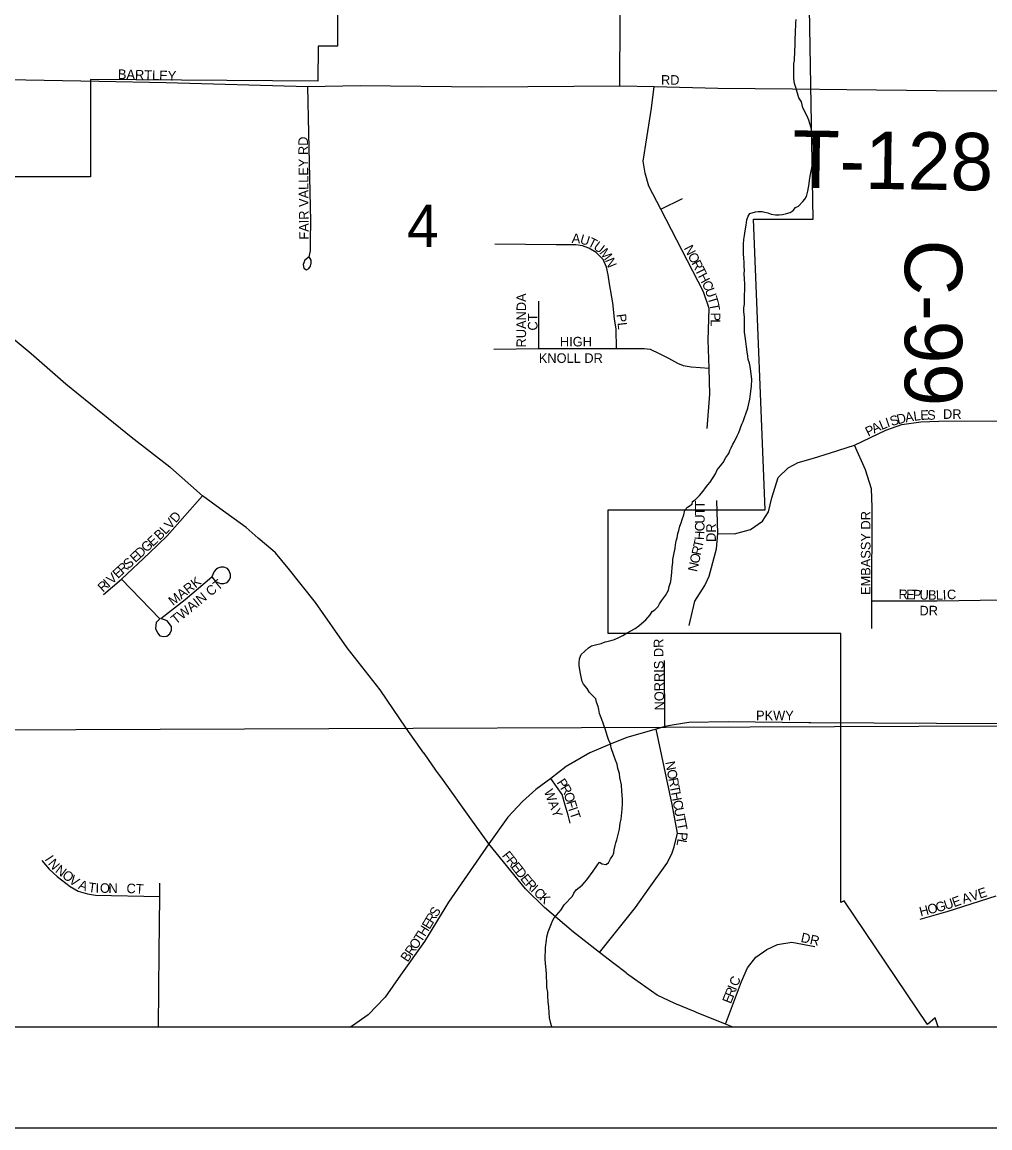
# Model space of a CAD drawing. Extents: x 8.5 to 81.5, y -1.2 to 22.4.
# Drawn here: x 51.227 to 52.184, y 14.351 to 15.445 of the extents above; entities that cross this region are included whole.
import ezdxf

# ---------------------------------------------------------------- set-up
doc = ezdxf.new("R2010")
doc.units = 0
for name, color, linetype in [('GM_X_City_Street', 7, 'Continuous'), ('GM_X_City_Street_Text', 7, 'Continuous'), ('GM_X_Corporation', 7, 'Continuous'), ('GM_X_County', 7, 'Continuous'), ('GM_X_County_Road', 7, 'Continuous'), ('GM_X_County_Road_Text', 7, 'Continuous'), ('GM_X_Minor_River', 7, 'Continuous'), ('GM_X_Section', 7, 'Continuous'), ('GM_X_Section_Text', 7, 'Continuous'), ('GM_X_Township', 7, 'Continuous'), ('GM_X_Township_Road', 7, 'Continuous'), ('GM_X_Township_Road_Text', 7, 'Continuous'), ('GM_X_Township_Subdivision', 7, 'Continuous'), ('GM_X_Township_Subdivision_Text', 7, 'Continuous'), ('SH_Data', 7, 'Continuous')]:
    doc.layers.add(name, color=color, linetype=linetype)

msp = doc.modelspace()

# ---------------------------------------------------------------- linework, layer by layer
at = {"layer": 'GM_X_City_Street'}
for points in [[(51.8184, 15.3819), (51.8187, 15.4496), (51.8192, 15.5596), (51.8199, 15.5865), (51.8185, 15.5979), (51.8172, 15.6073), (51.8137, 15.6169), (51.804, 15.6315), (51.7923, 15.6432), (51.7791, 15.6529), (51.7646, 15.6584), (51.7518, 15.6615), (51.7335, 15.6612), (51.6527, 15.6609)], [(51.3031, 15.3865), (51.3695, 15.3852), (51.5095, 15.3812), (51.5614, 15.3822), (51.6817, 15.381), (51.8184, 15.3819), (51.8522, 15.3812), (51.9151, 15.3797), (51.9892, 15.3789)], [(51.5109, 15.2126), (51.5065, 15.2093), (51.505, 15.2052), (51.5057, 15.2014), (51.5083, 15.1999), (51.5106, 15.201), (51.5121, 15.2033), (51.5129, 15.2063), (51.5129, 15.2095), (51.5109, 15.2126), (51.5121, 15.2186), (51.5122, 15.2294), (51.5124, 15.2478), (51.5106, 15.3349), (51.5095, 15.3812)], [(51.9048, 15.0429), (51.9075, 15.0769), (51.9066, 15.1026), (51.9057, 15.1302), (51.9066, 15.1614), (51.9011, 15.1779), (51.8588, 15.2597), (51.8469, 15.2826), (51.8432, 15.2955), (51.8414, 15.3074), (51.8451, 15.3304), (51.8497, 15.3598), (51.8522, 15.3812)], [(51.8588, 15.2597), (51.8802, 15.2705)], [(51.3735, 15.004), (51.373, 15.0044), (51.3347, 15.0342), (51.3066, 15.0568), (51.27, 15.0866), (51.2359, 15.1168), (51.2201, 15.13), (51.2001, 15.1505), (51.169, 15.1863), (51.1432, 15.2208), (51.1225, 15.2467), (51.1174, 15.2524)], [(51.815, 15.1221), (51.8146, 15.141), (51.8131, 15.1512), (51.8112, 15.167), (51.8082, 15.1859), (51.8067, 15.1949), (51.8052, 15.2025), (51.8018, 15.21), (51.795, 15.2168), (51.7875, 15.2213), (51.7814, 15.2236), (51.7746, 15.2247), (51.7554, 15.2247), (51.6947, 15.2251)], [(51.7381, 15.1221), (51.7381, 15.1687)], [(51.6935, 15.1214), (51.7381, 15.1221), (51.815, 15.1221), (51.8422, 15.1218), (51.8482, 15.1214), (51.8572, 15.1169), (51.8663, 15.1123), (51.8753, 15.1074), (51.881, 15.1052), (51.8889, 15.1037), (51.9066, 15.1026)], [(51.4748, 14.9221), (51.4604, 14.9343), (51.4484, 14.9447), (51.4225, 14.9637), (51.4052, 14.976), (51.3735, 15.004)], [(51.3072, 14.8784), (51.3252, 14.8938), (51.3524, 14.9195), (51.3704, 14.9364), (51.4052, 14.976)], [(51.6245, 14.7214), (51.607, 14.7462), (51.5811, 14.7841), (51.5484, 14.8256), (51.5171, 14.8705), (51.4902, 14.9046), (51.4775, 14.9198), (51.4748, 14.9221)], [(51.3252, 14.8938), (51.3631, 14.8543), (51.3594, 14.8509), (51.3589, 14.8448), (51.3609, 14.8404), (51.363, 14.8376), (51.3671, 14.8368), (51.3699, 14.8373), (51.373, 14.8396), (51.3748, 14.843), (51.3745, 14.8468), (51.3704, 14.8525), (51.3642, 14.8546), (51.3881, 14.8735), (51.4146, 14.8959), (51.4182, 14.8912), (51.4231, 14.8892), (51.4264, 14.8892), (51.4297, 14.8905), (51.4318, 14.8925), (51.4331, 14.8956), (51.4331, 14.8984), (51.4318, 14.902), (51.43, 14.9043), (51.4264, 14.9054), (51.4236, 14.9054), (51.4205, 14.9046), (51.4192, 14.9036), (51.4189, 14.9036), (51.4169, 14.9013), (51.4156, 14.8982), (51.4146, 14.8959)], [(51.8629, 14.7479), (51.8625, 14.8132)], [(52.0052, 14.7513), (51.9257, 14.7523), (51.8867, 14.7518), (51.8721, 14.7495), (51.8629, 14.7479), (51.8542, 14.7453), (51.8252, 14.7368), (51.8079, 14.73), (51.7886, 14.7216), (51.7652, 14.7083), (51.7501, 14.6963), (51.7351, 14.6853), (51.722, 14.6737), (51.7076, 14.6582), (51.6887, 14.6317)], [(51.7982, 14.5242), (51.8337, 14.5687), (51.8472, 14.5877), (51.8647, 14.6122), (51.8697, 14.6217), (51.8722, 14.6287), (51.8752, 14.6422), (51.8702, 14.6707), (51.8542, 14.7453)], [(51.6419, 14.6969), (51.6363, 14.7047), (51.6246, 14.7213), (51.6245, 14.7214)], [(51.6887, 14.6317), (51.6708, 14.6564), (51.642, 14.6967), (51.6419, 14.6969)], [(51.769, 14.6522), (51.7671, 14.6601), (51.7641, 14.6699), (51.7611, 14.6805), (51.7501, 14.6963)], [(51.6887, 14.6317), (51.6487, 14.574), (51.625, 14.535), (51.6012, 14.5016), (51.586, 14.4799), (51.5692, 14.4626), (51.5537, 14.4514), (51.5522, 14.4506)], [(51.77, 14.5462), (51.7436, 14.5687), (51.7251, 14.5872), (51.6887, 14.6317)], [(51.2463, 14.6151), (51.2535, 14.6066), (51.2614, 14.5994), (51.2745, 14.5895), (51.2824, 14.5849), (51.2916, 14.5823), (51.2995, 14.581), (51.3631, 14.5797)], [(51.3619, 14.4506), (51.3626, 14.5245), (51.3631, 14.5797), (51.3632, 14.5928)], [(51.8245, 14.5039), (51.8122, 14.5131), (51.7982, 14.5242), (51.7707, 14.5456), (51.77, 14.5462)], [(51.9227, 14.4532), (51.9387, 14.4953), (51.9447, 14.5089), (51.953, 14.5194), (51.9636, 14.527), (51.9742, 14.5322), (51.9885, 14.5345), (52.0111, 14.53)], [(51.8928, 14.4653), (51.8727, 14.4737), (51.8553, 14.482), (51.8328, 14.4976), (51.8249, 14.5035), (51.8245, 14.5039)], [(51.9295, 14.4506), (51.9227, 14.4532), (51.8942, 14.4647), (51.8928, 14.4653)]]:
    msp.add_lwpolyline(points, dxfattribs=at)
at = {"layer": 'GM_X_Corporation'}
msp.add_line((51.0687, 14.4506), (52.1333, 14.4506), dxfattribs=at)
for points in [[(51.5389, 15.7615), (51.5388, 15.4213), (51.5199, 15.4213), (51.5194, 15.3866), (51.2944, 15.3882), (51.2945, 15.2917), (51.1966, 15.2917)], [(52.1333, 14.4506), (52.1304, 14.4594), (52.1227, 14.453), (52.0404, 14.5752), (52.037, 14.5736), (52.037, 14.8399), (51.8069, 14.84), (51.8069, 14.9622), (51.9622, 14.9622), (51.9504, 15.25), (52.0096, 15.25), (52.0006, 15.7624)]]:
    msp.add_lwpolyline(points, dxfattribs=at)
at = {"layer": 'GM_X_County'}
msp.add_lwpolyline([(54.0879, 21.2506), (49.4527, 21.2506), (49.4527, 14.4506), (56.2527, 14.4506), (56.2527, 19.1108)], dxfattribs=at)
at = {"layer": 'GM_X_County_Road'}
msp.add_lwpolyline([(52.1939, 14.7505), (52.0072, 14.7513), (52.0052, 14.7513)], dxfattribs=at)
at = {"layer": 'GM_X_Minor_River'}
for points in [[(51.9905, 15.404), (51.991, 15.4071), (51.991, 15.4101), (51.9915, 15.4135), (51.992, 15.4371), (51.9924, 15.4409), (51.9925, 15.4443), (51.9929, 15.4477)], [(51.9053, 14.9869), (51.9076, 14.9895), (51.9131, 14.9978), (51.9147, 15.002), (51.9178, 15.0057), (51.9205, 15.0091), (51.9233, 15.014), (51.926, 15.0181), (51.9272, 15.0211), (51.9284, 15.0237), (51.93, 15.0271), (51.9319, 15.0298), (51.9343, 15.0354), (51.9359, 15.0388), (51.9391, 15.0471), (51.9403, 15.0498), (51.9419, 15.0547), (51.9431, 15.0573), (51.9448, 15.063), (51.9456, 15.066), (51.9464, 15.0687), (51.9469, 15.0717), (51.9477, 15.077), (51.9486, 15.0846), (51.9488, 15.0911), (51.9478, 15.0994), (51.9471, 15.104), (51.9465, 15.1075), (51.9454, 15.1109), (51.9451, 15.1143), (51.9444, 15.1185), (51.9437, 15.1235), (51.9431, 15.1288), (51.9424, 15.1338), (51.9418, 15.138), (51.9418, 15.141), (51.9416, 15.146), (51.9417, 15.1528), (51.9411, 15.1585), (51.9411, 15.1623), (51.9416, 15.1658), (51.9418, 15.176), (51.9419, 15.1787), (51.942, 15.1855), (51.9417, 15.1909), (51.9414, 15.1958), (51.9415, 15.1996), (51.9412, 15.203), (51.9413, 15.2065), (51.941, 15.2122), (51.9407, 15.2148), (51.9408, 15.2175), (51.9405, 15.2221), (51.9405, 15.2251), (51.941, 15.2297), (51.9415, 15.2339), (51.9423, 15.2384), (51.9432, 15.2441), (51.9441, 15.2494), (51.9453, 15.2528), (51.9468, 15.2554), (51.9526, 15.2572), (51.9552, 15.2575), (51.959, 15.2575), (51.9617, 15.257), (51.9647, 15.2562), (51.9681, 15.255), (51.9722, 15.2542), (51.976, 15.2541), (51.9791, 15.2544), (51.9833, 15.2554), (51.9867, 15.2565), (51.9898, 15.2584), (51.9921, 15.2614), (51.9952, 15.2628), (51.9995, 15.2673), (52.0014, 15.2699), (52.003, 15.2725), (52.0042, 15.2775), (52.0055, 15.285), (52.006, 15.2885), (52.0068, 15.2941), (52.0085, 15.3025), (52.009, 15.3074), (52.0095, 15.3146), (52.01, 15.3177), (52.0101, 15.3211), (52.0094, 15.326), (52.0084, 15.3337), (52.0078, 15.3386), (52.0074, 15.3413), (52.0053, 15.3478), (52.0035, 15.352), (51.9995, 15.3601), (51.9981, 15.3662), (51.9955, 15.3701), (51.9923, 15.3804), (51.9912, 15.3842), (51.9906, 15.3892), (51.9903, 15.393), (51.9905, 15.404)], [(51.7981, 14.6135), (51.8007, 14.6119), (51.8045, 14.6111), (51.8072, 14.613), (51.8092, 14.6167), (51.8112, 14.6201), (51.8123, 14.6228), (51.8128, 14.6258), (51.8136, 14.63), (51.8144, 14.6326), (51.8153, 14.6356), (51.8169, 14.6424), (51.8178, 14.6462), (51.8187, 14.6523), (51.8195, 14.6561), (51.8199, 14.6595), (51.8205, 14.666), (51.8209, 14.6713), (51.821, 14.6755), (51.8207, 14.68), (51.8204, 14.6835), (51.8198, 14.69), (51.8184, 14.6972), (51.8178, 14.7014), (51.8164, 14.7064), (51.8157, 14.7106), (51.8139, 14.7144), (51.8124, 14.719), (51.8096, 14.7267), (51.8089, 14.7305), (51.8071, 14.7351), (51.806, 14.7378), (51.8039, 14.7455), (51.8024, 14.7493), (51.8014, 14.752), (51.7992, 14.7581), (51.7981, 14.7608), (51.7974, 14.7646), (51.7968, 14.7677), (51.7953, 14.7719), (51.7946, 14.7753), (51.792, 14.7777), (51.7883, 14.7815), (51.7861, 14.7854), (51.7824, 14.7897), (51.7809, 14.7923), (51.7803, 14.7954), (51.7792, 14.8004), (51.7779, 14.808), (51.7779, 14.8107), (51.7784, 14.8148), (51.78, 14.819), (51.7873, 14.8257), (51.7904, 14.8275), (51.7954, 14.829), (51.7999, 14.83), (51.8038, 14.8315), (51.8083, 14.8325), (51.8129, 14.8339), (51.8179, 14.8361), (51.8214, 14.838), (51.8256, 14.8405), (51.8333, 14.8449), (51.8371, 14.8475), (51.8398, 14.8498), (51.8441, 14.8535), (51.8483, 14.8583), (51.8503, 14.8617), (51.853, 14.8632), (51.8561, 14.8665), (51.8577, 14.8692), (51.8596, 14.8722), (51.8635, 14.8774), (51.8663, 14.8827), (51.8671, 14.8865), (51.8688, 14.8914), (51.8692, 14.8944), (51.8697, 14.9001), (51.8702, 14.9055), (51.8707, 14.91), (51.8707, 14.9131), (51.8716, 14.918), (51.8729, 14.9244), (51.8733, 14.9275), (51.8741, 14.9316), (51.875, 14.9347), (51.8758, 14.9388), (51.8766, 14.9419), (51.8778, 14.946), (51.8791, 14.9494), (51.8799, 14.9528), (51.8815, 14.9574), (51.8827, 14.9619), (51.8854, 14.9649), (51.8897, 14.9678), (51.8901, 14.9705), (51.8928, 14.9723), (51.8971, 14.9764), (51.9006, 14.9806), (51.9029, 14.9839), (51.9053, 14.9869)], [(51.7509, 14.4506), (51.75, 14.4539), (51.7486, 14.4596), (51.7481, 14.4699), (51.7474, 14.4756), (51.7472, 14.481), (51.7469, 14.4848), (51.7462, 14.4894), (51.7459, 14.4943), (51.7457, 14.5004), (51.7457, 14.5031), (51.7454, 14.5065), (51.7448, 14.5137), (51.7445, 14.5172), (51.7448, 14.529), (51.7457, 14.5362), (51.7461, 14.5396), (51.7474, 14.5445), (51.7506, 14.5528), (51.7518, 14.5555), (51.7533, 14.5585), (51.7603, 14.5663), (51.7631, 14.5712), (51.7716, 14.5798), (51.7728, 14.5828), (51.7752, 14.5862), (51.7809, 14.5907), (51.7856, 14.5959), (51.7919, 14.6045), (51.7962, 14.6109), (51.7981, 14.6135)]]:
    msp.add_lwpolyline(points, dxfattribs=at)
at = {"layer": 'GM_X_Section'}
msp.add_line((51.1937, 14.4506), (52.195, 14.4506), dxfattribs=at)
msp.add_lwpolyline([(51.1955, 15.7645), (52.2033, 15.7642), (52.1975, 14.7482), (51.1961, 14.7442)], close=True, dxfattribs=at)
msp.add_lwpolyline([(52.195, 14.4506), (52.1975, 14.7482), (51.1961, 14.7442), (51.1937, 14.4506)], dxfattribs=at)
at = {"layer": 'GM_X_Township'}
msp.add_lwpolyline([(49.4527, 15.7601), (49.4527, 14.4506), (54.4602, 14.4506)], dxfattribs=at)
at = {"layer": 'GM_X_Township_Road'}
for points in [[(51.1938, 15.3886), (51.3031, 15.3865)], [(51.9892, 15.3789), (51.9893, 15.3789), (52.0428, 15.3784), (52.1312, 15.3772), (52.198, 15.3769)]]:
    msp.add_lwpolyline(points, dxfattribs=at)
at = {"layer": 'GM_X_Township_Subdivision'}
for points in [[(51.9151, 14.939), (51.9318, 14.9385), (51.9476, 14.9429), (51.9594, 14.951), (51.9655, 14.9602), (51.9688, 14.974), (51.975, 14.9941), (51.9847, 15.0038), (51.9949, 15.0091), (52.0099, 15.0134), (52.0268, 15.0186), (52.0504, 15.0262), (52.0814, 15.041), (52.0973, 15.0466), (52.1161, 15.0494), (52.1341, 15.05), (52.1974, 15.0504)], [(52.0675, 14.8449), (52.0677, 14.8719), (52.0679, 14.965), (52.0673, 14.9832), (52.0615, 15.0018), (52.0504, 15.0262)], [(51.8868, 14.8477), (51.8924, 14.8719), (51.9024, 14.8873), (51.9067, 14.8967), (51.9104, 14.9102), (51.9138, 14.9235), (51.9151, 14.939), (51.9142, 14.9716)], [(52.1964, 14.8728), (52.1322, 14.8717), (52.0677, 14.8719)], [(52.1408, 14.5643), (52.1423, 14.5648), (52.1908, 14.5803)], [(52.1156, 14.5571), (52.1408, 14.5643)]]:
    msp.add_lwpolyline(points, dxfattribs=at)
at = {"layer": 'SH_Data'}
for p, q in [((49.4527, 14.4506), (56.2527, 14.4506)), ((49.3527, 14.3506), (56.3527, 14.3506))]:
    msp.add_line(p, q, dxfattribs=at)

# ---------------------------------------------------------------- texts
at = {"layer": 'GM_X_City_Street_Text'}
for s, rotation, p in [('BARTLEY', 358.211, (51.3215, 15.3888)), ('RD', 0, (51.859, 15.383)), ('FAIR VALLEY RD', 90.5087, (51.5105, 15.2297)), ('A', 356.545, (51.7705, 15.2265)), ('U', 343.7424, (51.7782, 15.2261)), ('T', 333.2394, (51.7858, 15.2239)), ('U', 322.9072, (51.7914, 15.2211)), ('N', 296.9462, (51.8814, 15.2213)), ('M', 308.1705, (51.7976, 15.2166)), ('O', 296.9829, (51.8852, 15.2139)), ('N', 292.524, (51.8034, 15.2093)), ('R', 296.9669, (51.8889, 15.2065)), ('T', 296.9439, (51.8923, 15.1998)), ('H', 296.9677, (51.8954, 15.1938)), ('C', 296.0438, (51.8991, 15.1864)), ('U', 289.4788, (51.9023, 15.18)), ('RUANDA', 90, (51.7255, 15.123)), ('T', 286.3695, (51.905, 15.1722)), ('T', 280.4955, (51.9069, 15.1661)), ('CT', 90, (51.7368, 15.1397)), ('PL', 276.7069, (51.8149, 15.1557)), ('P', 270.4645, (51.9082, 15.1575)), ('L', 270, (51.9082, 15.1508)), ('HIGH', 0, (51.759, 15.124)), ('KNOLL DR', 0, (51.7381, 15.1077)), ('V', 48.9249, (51.3735, 14.9424)), ('D', 48.9883, (51.379, 14.9487)), ('B', 43.2578, (51.3628, 14.9316)), ('L', 47.264, (51.3688, 14.9373)), ('G', 42.6267, (51.3498, 14.9197)), ('E', 42.6454, (51.356, 14.9253)), ('E', 42.6454, (51.3388, 14.9095)), ('D', 42.6192, (51.3437, 14.914)), ('R', 42.6358, (51.3265, 14.8982)), ('S', 42.643, (51.3321, 14.9033)), ('V', 42.6501, (51.3155, 14.8881)), ('E', 42.6229, (51.3216, 14.8937)), ('MARK', 38.2372, (51.3762, 14.8669)), ('R', 42.6298, (51.3069, 14.8802)), ('I', 42.644, (51.3124, 14.8852)), ('TWAIN CT', 38.9284, (51.3789, 14.8484)), ('NORRIS DR', 90.7738, (51.8622, 14.7638)), ('PKWY', 0, (51.9531, 14.754)), ('N', 280.7056, (51.8632, 14.7126)), ('O', 280.7056, (51.8647, 14.7044)), ('P', 303.1521, (51.7554, 14.6924)), ('R', 301.7634, (51.759, 14.6869)), ('R', 280.7002, (51.8663, 14.6962)), ('T', 280.6885, (51.8677, 14.6888)), ('WAY', 291.0371, (51.7429, 14.6836)), ('O', 286.693, (51.7627, 14.6811)), ('H', 280.7056, (51.8689, 14.6823)), ('F', 286.3695, (51.7651, 14.6731)), ('I', 288.6316, (51.7671, 14.6663)), ('C', 280.7241, (51.8705, 14.6741)), ('U', 280.6841, (51.8719, 14.6667)), ('T', 289.2198, (51.7684, 14.6623)), ('T', 280.7131, (51.8734, 14.6585)), ('T', 280.7153, (51.8747, 14.6519)), ('L', 259.6438, (51.8756, 14.6372)), ('P', 265.8443, (51.876, 14.6436)), ('F', 308.3398, (51.7012, 14.6199)), ('I', 303.1082, (51.2488, 14.6164)), ('N', 310.3963, (51.2519, 14.6119)), ('N', 323.168, (51.2589, 14.604)), ('R', 308.3314, (51.7053, 14.6147)), ('E', 308.3611, (51.71, 14.6088)), ('O', 322.61, (51.2656, 14.599)), ('V', 324.1079, (51.2724, 14.5938)), ('D', 308.3389, (51.7141, 14.6036)), ('E', 308.3437, (51.7193, 14.5971)), ('A', 340.3039, (51.2818, 14.5875)), ('T', 352.6168, (51.2918, 14.5842)), ('I', 358.5809, (51.2994, 14.5833)), ('O', 359.7337, (51.3038, 14.5832)), ('N', 359.9929, (51.3122, 14.5831)), ('CT', 356.8222, (51.3299, 14.5831)), ('R', 312.2147, (51.7239, 14.5913)), ('I', 316.1289, (51.7294, 14.5852)), ('C', 316.4827, (51.7324, 14.5823)), ('K', 316.5767, (51.7379, 14.5771)), ('S', 58.6754, (51.6372, 14.5585)), ('E', 58.6652, (51.6299, 14.5464)), ('R', 58.684, (51.6333, 14.5521)), ('H', 58.6047, (51.6255, 14.5393)), ('O', 55.4224, (51.6169, 14.5264)), ('T', 57.2335, (51.6218, 14.5335)), ('DR', 347.4673, (51.9968, 14.5347)), ('B', 55.3402, (51.6083, 14.514)), ('R', 55.3514, (51.6126, 14.5202)), ('I', 68.4665, (51.9333, 14.486)), ('C', 67.892, (51.9348, 14.4899)), ('E', 68.4878, (51.9281, 14.4728)), ('R', 68.493, (51.9306, 14.479))]:
    msp.add_text(s, height=0.00947, rotation=rotation, dxfattribs=at).set_placement(p)
at = {"layer": 'GM_X_County_Road_Text'}
msp.add_text('C-99', height=0.05682, rotation=270, dxfattribs=at).set_placement((52.1002, 15.2297))
at = {"layer": 'GM_X_Section_Text'}
msp.add_text('4', height=0.0419, rotation=0, dxfattribs=at).set_placement((51.6077, 15.2225))
at = {"layer": 'GM_X_Township_Road_Text'}
msp.add_text('T-128', height=0.05682, rotation=359.1569, dxfattribs=at).set_placement((51.9889, 15.2811))
at = {"layer": 'GM_X_Township_Subdivision_Text'}
for s, rotation, p in [('L', 8.1958, (52.1095, 15.0502)), ('E', 2.3234, (52.1158, 15.0512)), ('S', 0.1639, (52.1224, 15.0514)), ('DR', 0, (52.1381, 15.0523)), ('L', 22.5778, (52.0773, 15.0412)), ('I', 18.3658, (52.0832, 15.0437)), ('S', 17.3377, (52.0872, 15.045)), ('D', 13.2993, (52.0934, 15.0469)), ('A', 9.8611, (52.1013, 15.0488)), ('P', 26.4184, (52.064, 15.0346)), ('A', 26.434, (52.07, 15.0376)), ('T', 90, (51.9022, 14.9636)), ('T', 90, (51.9022, 14.9569)), ('U', 90.0154, (51.9022, 14.9486)), ('EMBASSY DR', 90, (52.0663, 14.878)), ('H', 86.9866, (51.9016, 14.9322)), ('C', 89.0915, (51.902, 14.9409)), ('DR', 90, (51.9133, 14.9305)), ('T', 77.4426, (51.8999, 14.924)), ('O', 77.4454, (51.8965, 14.9085)), ('R', 77.4441, (51.8983, 14.9167)), ('N', 77.4427, (51.8947, 14.9004)), ('R', 358.7858, (52.094, 14.874)), ('E', 358.7707, (52.1015, 14.8738)), ('P', 358.8012, (52.1082, 14.8737)), ('U', 358.776, (52.1148, 14.8735)), ('B', 359.1152, (52.1232, 14.8733)), ('L', 1.301, (52.1311, 14.8732)), ('I', 2.4285, (52.138, 14.8734)), ('C', 2.4752, (52.1422, 14.8736)), ('DR', 0, (52.1148, 14.8578)), ('AVE', 17.8169, (52.1584, 14.5722)), ('U', 18.2278, (52.1408, 14.5662)), ('E', 19.4262, (52.149, 14.5689)), ('H', 14.5133, (52.116, 14.5597)), ('O', 14.5317, (52.1241, 14.5618)), ('G', 14.8951, (52.1322, 14.5639))]:
    msp.add_text(s, height=0.00947, rotation=rotation, dxfattribs=at).set_placement(p)

doc.saveas('drawing.dxf')
